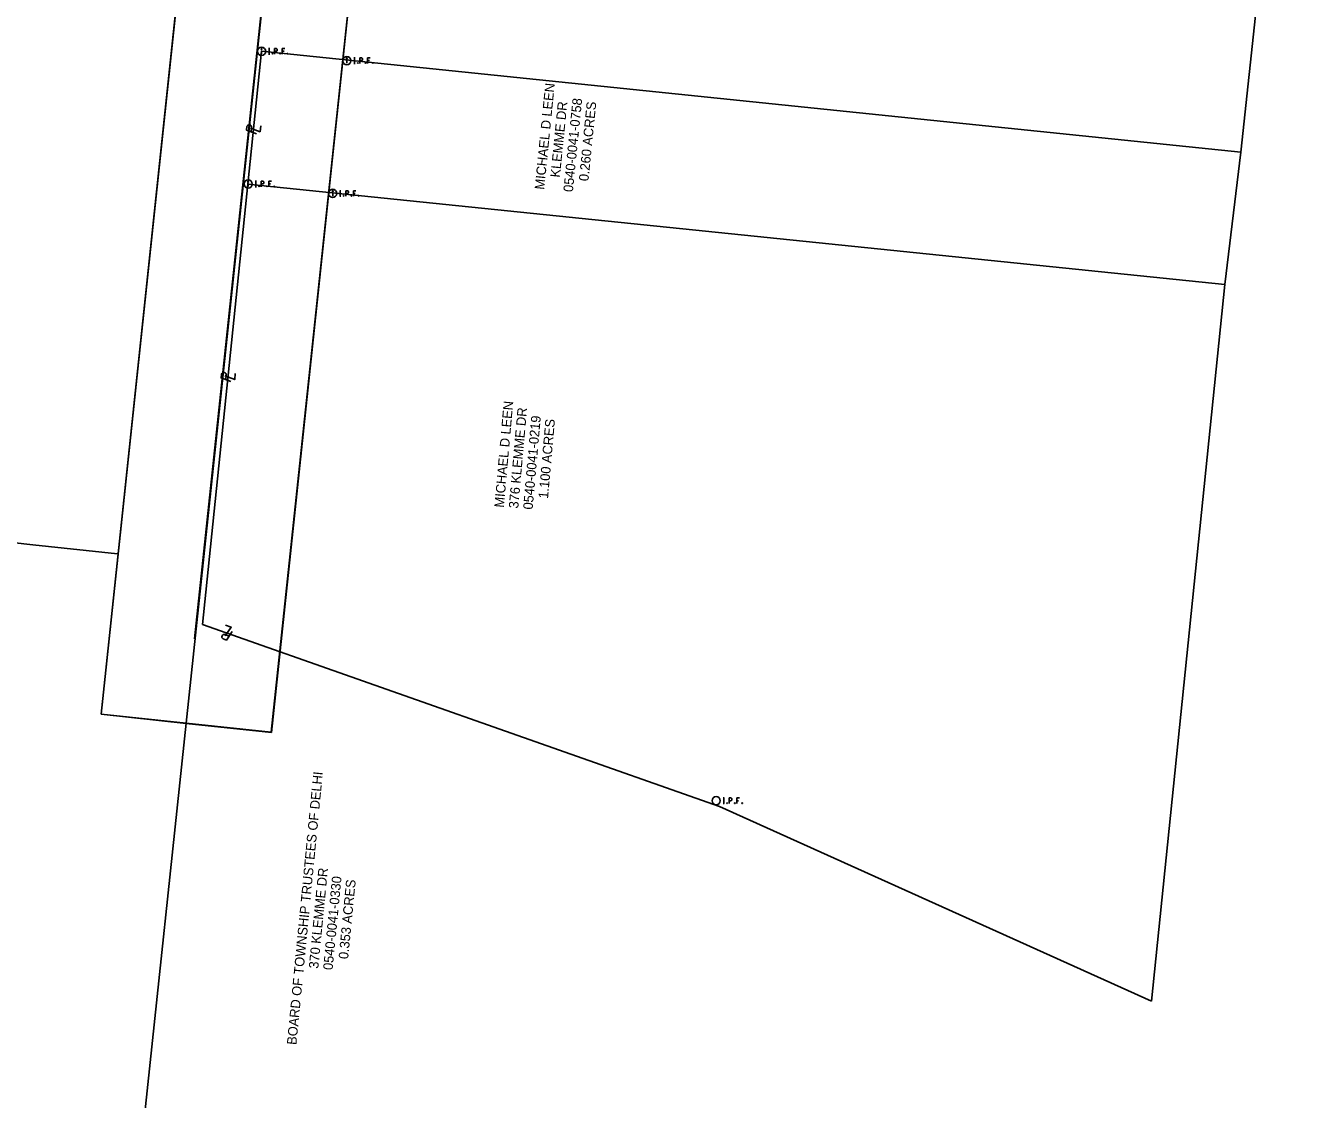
# Model space of a CAD drawing. Extents: x 1369159 to 1370720, y 404461 to 406422.
# Drawn here: x 1369919.6 to 1370296.1, y 405264.5 to 405577.8 of the extents above; entities that cross this region are included whole.
import ezdxf

# ---------------------------------------------------------------- set-up
doc = ezdxf.new("R2010")
doc.units = 0
for name, color, linetype in [('Default', 7, 'Continuous'), ('DR_P_Cells', 7, 'Continuous'), ('DR_P_Storm_Sewer', 7, 'Continuous'), ('GK_Drainage_Nodes', 7, 'Continuous'), ('PF_X_Ground_Line', 7, 'Continuous'), ('SC_Scratch1', 7, 'Continuous'), ('UT_X_Water', 7, 'Continuous'), ('XS_X_Pavt', 7, 'Continuous'), ('XS_X_Subgrade', 7, 'Continuous')]:
    doc.layers.add(name, color=color, linetype=linetype)

msp = doc.modelspace()

# ---------------------------------------------------------------- linework, layer by layer
at = {"layer": 'Default'}
for p, q in [((1369984.48, 405531.6), (1369988.46, 405570.34)), ((1369988.46, 405570.34), (1370274.45, 405540.93)), ((1370274.45, 405540.93), (1370269.79, 405502.27)), ((1369971.26, 405403.08), (1369984.48, 405531.6)), ((1370269.79, 405502.27), (1369984.48, 405531.61)), ((1370269.79, 405502.27), (1370248.29, 405293.15)), ((1370122.22, 405349.97), (1369971.26, 405403.08)), ((1369966.45, 405374.29), (1369897.64, 404726.71)), ((1370248.29, 405293.15), (1370122.22, 405349.97))]:
    msp.add_line(p, q, dxfattribs=at)
at = {"layer": 'DR_P_Cells'}
for p, q in [((1370077.92, 406421.94), (1369968.9, 405398.85)), ((1369966.45, 405374.29), (1369869.42, 404461.09))]:
    msp.add_line(p, q, dxfattribs=at)
at = {"layer": 'DR_P_Storm_Sewer'}
for p, q in [((1370274.45, 405540.93), (1370296.13, 405744.87)), ((1369985.42, 405546.84), (1369985.55, 405548.13)), ((1369986.12, 405547.58), (1369986.12, 405547.58)), ((1369977.98, 405474.54), (1369978.12, 405475.83)), ((1369978.68, 405475.27), (1369978.68, 405475.27)), ((1369978.99, 405399.7), (1369977.76, 405400.13)), ((1369978.44, 405400.55), (1369978.44, 405400.55))]:
    msp.add_line(p, q, dxfattribs=at)
for points in [[(1369986.96, 405546.26), (1369984.09, 405547.34), (1369984.2, 405548.37)], [(1369985.19, 405547.94), (1369988.05, 405546.85), (1369988.23, 405548.59)], [(1369979.52, 405473.96), (1369976.65, 405475.04), (1369976.76, 405476.06)], [(1369977.76, 405475.63), (1369980.62, 405474.54), (1369980.8, 405476.28)], [(1369977.87, 405399.74), (1369979.59, 405402.26), (1369977.95, 405402.84)], [(1369979.91, 405401.06), (1369978.19, 405398.52), (1369977.21, 405398.87)]]:
    msp.add_lwpolyline(points, dxfattribs=at)
for centre, start, end in [((1369984.87, 405548.2), 354.5992, 165.4563), ((1369977.43, 405475.89), 354.5992, 165.4563), ((1369977.54, 405399.48), 71.0908, 241.9479)]:
    msp.add_arc(centre, 0.69, start, end, dxfattribs=at)
at = {"layer": 'PF_X_Ground_Line'}
msp.add_lwpolyline([(1369946.39, 405423.64), (1369921.62, 405426.31), (1369638.99, 405458.25)], dxfattribs=at)
at = {"layer": 'SC_Scratch1'}
for p, q in [((1369988.46, 405570.46), (1369988.46, 405569.57)), ((1369990.49, 405571.14), (1369990.85, 405571.14)), ((1369990.49, 405569.54), (1369990.85, 405569.54)), ((1369990.67, 405569.54), (1369990.67, 405571.14)), ((1369991.56, 405569.68), (1369991.59, 405569.73)), ((1369991.56, 405569.61), (1369991.56, 405569.68)), ((1369991.59, 405569.56), (1369991.56, 405569.61)), ((1369991.59, 405569.73), (1369991.63, 405569.75)), ((1369991.63, 405569.54), (1369991.59, 405569.56)), ((1369991.63, 405569.75), (1369991.68, 405569.75)), ((1369991.68, 405569.54), (1369991.63, 405569.54)), ((1369991.68, 405569.75), (1369991.72, 405569.73)), ((1369991.72, 405569.56), (1369991.68, 405569.54)), ((1369991.72, 405569.73), (1369991.75, 405569.68)), ((1369991.75, 405569.61), (1369991.72, 405569.56)), ((1369991.75, 405569.68), (1369991.75, 405569.61)), ((1369992.23, 405569.54), (1369992.23, 405571.14)), ((1369992.23, 405571.14), (1369992.76, 405571.14)), ((1369992.76, 405570.36), (1369992.23, 405570.36)), ((1369992.76, 405571.14), (1369992.82, 405571.13)), ((1369992.85, 405570.37), (1369992.76, 405570.36)), ((1369992.82, 405571.13), (1369992.9, 405571.1)), ((1369992.91, 405570.4), (1369992.85, 405570.37)), ((1369992.9, 405571.1), (1369992.93, 405571.08)), ((1369992.94, 405570.42), (1369992.91, 405570.4)), ((1369992.93, 405571.08), (1369992.96, 405571.05)), ((1369992.98, 405570.46), (1369992.94, 405570.42)), ((1369992.96, 405571.05), (1369993.01, 405570.99)), ((1369993.03, 405570.55), (1369992.98, 405570.46)), ((1369993.01, 405570.99), (1369993.04, 405570.92)), ((1369993.05, 405570.62), (1369993.03, 405570.55)), ((1369993.04, 405570.92), (1369993.06, 405570.82)), ((1369993.06, 405570.67), (1369993.05, 405570.62)), ((1369993.06, 405570.82), (1369993.06, 405570.67)), ((1369993.81, 405569.68), (1369993.84, 405569.73)), ((1369993.81, 405569.61), (1369993.81, 405569.68)), ((1369993.84, 405569.56), (1369993.81, 405569.61)), ((1369993.84, 405569.73), (1369993.88, 405569.75)), ((1369993.88, 405569.54), (1369993.84, 405569.56)), ((1369993.88, 405569.75), (1369993.93, 405569.75)), ((1369993.93, 405569.54), (1369993.88, 405569.54)), ((1369993.93, 405569.75), (1369993.96, 405569.73)), ((1369993.96, 405569.56), (1369993.93, 405569.54)), ((1369993.96, 405569.73), (1369994, 405569.68)), ((1369994, 405569.61), (1369993.96, 405569.56)), ((1369994, 405569.68), (1369994, 405569.61)), ((1369995.24, 405571.14), (1369994.48, 405571.14)), ((1369994.48, 405571.14), (1369994.48, 405569.54)), ((1369994.48, 405570.36), (1369995.02, 405570.36)), ((1369995.96, 405569.68), (1369995.99, 405569.73)), ((1369995.96, 405569.61), (1369995.96, 405569.68)), ((1369995.99, 405569.56), (1369995.96, 405569.61)), ((1369995.99, 405569.73), (1369996.03, 405569.75)), ((1369996.03, 405569.54), (1369995.99, 405569.56)), ((1369996.03, 405569.75), (1369996.08, 405569.75)), ((1369996.08, 405569.54), (1369996.03, 405569.54)), ((1369996.08, 405569.75), (1369996.11, 405569.73)), ((1369996.11, 405569.56), (1369996.08, 405569.54)), ((1369996.11, 405569.73), (1369996.15, 405569.68)), ((1369996.15, 405569.61), (1369996.11, 405569.56)), ((1369996.15, 405569.68), (1369996.15, 405569.61)), ((1370015.4, 405568.41), (1370015.76, 405568.41)), ((1370015.58, 405566.81), (1370015.58, 405568.41)), ((1370017.14, 405566.81), (1370017.14, 405568.41)), ((1370017.14, 405568.41), (1370017.67, 405568.41)), ((1370017.67, 405568.41), (1370017.73, 405568.4)), ((1370017.73, 405568.4), (1370017.81, 405568.37)), ((1370017.81, 405568.37), (1370017.84, 405568.35)), ((1370017.84, 405568.35), (1370017.87, 405568.32)), ((1370017.87, 405568.32), (1370017.92, 405568.26)), ((1370017.92, 405568.26), (1370017.95, 405568.2)), ((1370017.95, 405568.2), (1370017.97, 405568.09)), ((1370017.97, 405567.94), (1370017.96, 405567.89)), ((1370017.97, 405568.09), (1370017.97, 405567.94)), ((1370020.15, 405568.41), (1370019.39, 405568.41)), ((1370019.39, 405568.41), (1370019.39, 405566.81)), ((1370013.37, 405567.73), (1370013.37, 405566.84)), ((1370015.4, 405566.81), (1370015.76, 405566.81)), ((1370016.47, 405566.95), (1370016.5, 405567)), ((1370016.47, 405566.89), (1370016.47, 405566.95)), ((1370016.5, 405566.84), (1370016.47, 405566.89)), ((1370016.5, 405567), (1370016.54, 405567.02)), ((1370016.54, 405566.81), (1370016.5, 405566.84)), ((1370016.54, 405567.02), (1370016.59, 405567.02)), ((1370016.59, 405566.81), (1370016.54, 405566.81)), ((1370016.59, 405567.02), (1370016.63, 405567)), ((1370016.63, 405566.84), (1370016.59, 405566.81)), ((1370016.63, 405567), (1370016.66, 405566.95)), ((1370016.66, 405566.89), (1370016.63, 405566.84)), ((1370016.66, 405566.95), (1370016.66, 405566.89)), ((1370017.67, 405567.63), (1370017.14, 405567.63)), ((1370017.76, 405567.64), (1370017.67, 405567.63)), ((1370017.82, 405567.67), (1370017.76, 405567.64)), ((1370017.85, 405567.69), (1370017.82, 405567.67)), ((1370017.89, 405567.73), (1370017.85, 405567.69)), ((1370017.94, 405567.82), (1370017.89, 405567.73)), ((1370017.96, 405567.89), (1370017.94, 405567.82)), ((1370018.72, 405566.95), (1370018.75, 405567)), ((1370018.72, 405566.89), (1370018.72, 405566.95)), ((1370018.75, 405566.84), (1370018.72, 405566.89)), ((1370018.75, 405567), (1370018.79, 405567.02)), ((1370018.79, 405566.81), (1370018.75, 405566.84)), ((1370018.79, 405567.02), (1370018.84, 405567.02)), ((1370018.84, 405566.81), (1370018.79, 405566.81)), ((1370018.84, 405567.02), (1370018.87, 405567)), ((1370018.87, 405566.84), (1370018.84, 405566.81)), ((1370018.87, 405567), (1370018.91, 405566.95)), ((1370018.91, 405566.89), (1370018.87, 405566.84)), ((1370018.91, 405566.95), (1370018.91, 405566.89)), ((1370019.39, 405567.63), (1370019.93, 405567.63)), ((1370020.87, 405566.95), (1370020.9, 405567)), ((1370020.87, 405566.89), (1370020.87, 405566.95)), ((1370020.9, 405566.84), (1370020.87, 405566.89)), ((1370020.9, 405567), (1370020.94, 405567.02)), ((1370020.94, 405566.81), (1370020.9, 405566.84)), ((1370020.94, 405567.02), (1370020.99, 405567.02)), ((1370020.99, 405566.81), (1370020.94, 405566.81)), ((1370020.99, 405567.02), (1370021.02, 405567)), ((1370021.02, 405566.84), (1370020.99, 405566.81)), ((1370021.02, 405567), (1370021.06, 405566.95)), ((1370021.06, 405566.89), (1370021.02, 405566.84)), ((1370021.06, 405566.95), (1370021.06, 405566.89)), ((1369984.55, 405531.73), (1369984.55, 405530.85)), ((1369986.58, 405532.42), (1369986.94, 405532.42)), ((1369986.58, 405530.82), (1369986.94, 405530.82)), ((1369986.76, 405530.82), (1369986.76, 405532.42)), ((1369987.65, 405530.95), (1369987.68, 405531.01)), ((1369987.65, 405530.89), (1369987.65, 405530.95)), ((1369987.68, 405530.84), (1369987.65, 405530.89)), ((1369987.68, 405531.01), (1369987.72, 405531.03)), ((1369987.72, 405530.82), (1369987.68, 405530.84)), ((1369987.72, 405531.03), (1369987.77, 405531.03)), ((1369987.77, 405530.82), (1369987.72, 405530.82)), ((1369987.77, 405531.03), (1369987.81, 405531.01)), ((1369987.81, 405530.84), (1369987.77, 405530.82)), ((1369987.81, 405531.01), (1369987.84, 405530.95)), ((1369987.84, 405530.89), (1369987.81, 405530.84)), ((1369987.84, 405530.95), (1369987.84, 405530.89)), ((1369988.32, 405530.82), (1369988.32, 405532.42)), ((1369988.32, 405532.42), (1369988.85, 405532.42)), ((1369988.85, 405531.63), (1369988.32, 405531.63)), ((1369988.85, 405532.42), (1369988.91, 405532.4)), ((1369988.94, 405531.65), (1369988.85, 405531.63)), ((1369988.91, 405532.4), (1369988.99, 405532.38)), ((1369989, 405531.67), (1369988.94, 405531.65)), ((1369988.99, 405532.38), (1369989.02, 405532.35)), ((1369989.03, 405531.7), (1369989, 405531.67)), ((1369989.02, 405532.35), (1369989.05, 405532.33)), ((1369989.07, 405531.74), (1369989.03, 405531.7)), ((1369989.05, 405532.33), (1369989.1, 405532.26)), ((1369989.12, 405531.82), (1369989.07, 405531.74)), ((1369989.1, 405532.26), (1369989.13, 405532.2)), ((1369989.14, 405531.9), (1369989.12, 405531.82)), ((1369989.13, 405532.2), (1369989.15, 405532.1)), ((1369989.15, 405531.95), (1369989.14, 405531.9)), ((1369989.15, 405532.1), (1369989.15, 405531.95)), ((1369989.9, 405530.95), (1369989.93, 405531.01)), ((1369989.9, 405530.89), (1369989.9, 405530.95)), ((1369989.93, 405530.84), (1369989.9, 405530.89)), ((1369989.93, 405531.01), (1369989.97, 405531.03)), ((1369989.97, 405530.82), (1369989.93, 405530.84)), ((1369989.97, 405531.03), (1369990.02, 405531.03)), ((1369990.02, 405530.82), (1369989.97, 405530.82)), ((1369990.02, 405531.03), (1369990.05, 405531.01)), ((1369990.05, 405530.84), (1369990.02, 405530.82)), ((1369990.05, 405531.01), (1369990.09, 405530.95)), ((1369990.09, 405530.89), (1369990.05, 405530.84)), ((1369990.09, 405530.95), (1369990.09, 405530.89)), ((1369991.33, 405532.42), (1369990.57, 405532.42)), ((1369990.57, 405532.42), (1369990.57, 405530.82)), ((1369990.57, 405531.63), (1369991.11, 405531.63)), ((1369992.05, 405530.95), (1369992.08, 405531.01)), ((1369992.05, 405530.89), (1369992.05, 405530.95)), ((1369992.08, 405530.84), (1369992.05, 405530.89)), ((1369992.08, 405531.01), (1369992.12, 405531.03)), ((1369992.12, 405530.82), (1369992.08, 405530.84)), ((1369992.12, 405531.03), (1369992.17, 405531.03)), ((1369992.17, 405530.82), (1369992.12, 405530.82)), ((1369992.17, 405531.03), (1369992.2, 405531.01)), ((1369992.2, 405530.84), (1369992.17, 405530.82)), ((1369992.2, 405531.01), (1369992.24, 405530.95)), ((1369992.24, 405530.89), (1369992.2, 405530.84)), ((1369992.24, 405530.95), (1369992.24, 405530.89)), ((1370009.24, 405528.98), (1370009.24, 405528.1)), ((1370011.27, 405529.67), (1370011.63, 405529.67)), ((1370011.27, 405528.07), (1370011.63, 405528.07)), ((1370011.45, 405528.07), (1370011.45, 405529.67)), ((1370012.34, 405528.21), (1370012.38, 405528.26)), ((1370012.34, 405528.14), (1370012.34, 405528.21)), ((1370012.38, 405528.09), (1370012.34, 405528.14)), ((1370012.38, 405528.26), (1370012.41, 405528.28)), ((1370012.41, 405528.07), (1370012.38, 405528.09)), ((1370012.41, 405528.28), (1370012.46, 405528.28)), ((1370012.46, 405528.07), (1370012.41, 405528.07)), ((1370012.46, 405528.28), (1370012.5, 405528.26)), ((1370012.5, 405528.09), (1370012.46, 405528.07)), ((1370012.5, 405528.26), (1370012.53, 405528.21)), ((1370012.53, 405528.14), (1370012.5, 405528.09)), ((1370012.53, 405528.21), (1370012.53, 405528.14)), ((1370013.02, 405528.07), (1370013.02, 405529.67)), ((1370013.02, 405529.67), (1370013.55, 405529.67)), ((1370013.55, 405528.89), (1370013.02, 405528.89)), ((1370013.55, 405529.67), (1370013.6, 405529.65)), ((1370013.63, 405528.9), (1370013.55, 405528.89)), ((1370013.6, 405529.65), (1370013.68, 405529.63)), ((1370013.69, 405528.92), (1370013.63, 405528.9)), ((1370013.68, 405529.63), (1370013.71, 405529.6)), ((1370013.72, 405528.95), (1370013.69, 405528.92)), ((1370013.71, 405529.6), (1370013.74, 405529.58)), ((1370013.77, 405528.99), (1370013.72, 405528.95)), ((1370013.74, 405529.58), (1370013.79, 405529.52)), ((1370013.81, 405529.07), (1370013.77, 405528.99)), ((1370013.79, 405529.52), (1370013.82, 405529.45)), ((1370013.83, 405529.15), (1370013.81, 405529.07)), ((1370013.82, 405529.45), (1370013.84, 405529.35)), ((1370013.84, 405529.2), (1370013.83, 405529.15)), ((1370013.84, 405529.35), (1370013.84, 405529.2)), ((1370014.59, 405528.21), (1370014.63, 405528.26)), ((1370014.59, 405528.14), (1370014.59, 405528.21)), ((1370014.63, 405528.09), (1370014.59, 405528.14)), ((1370014.63, 405528.26), (1370014.66, 405528.28)), ((1370014.66, 405528.07), (1370014.63, 405528.09)), ((1370014.66, 405528.28), (1370014.71, 405528.28)), ((1370014.71, 405528.07), (1370014.66, 405528.07)), ((1370014.71, 405528.28), (1370014.75, 405528.26)), ((1370014.75, 405528.09), (1370014.71, 405528.07)), ((1370014.75, 405528.26), (1370014.78, 405528.21)), ((1370014.78, 405528.14), (1370014.75, 405528.09)), ((1370014.78, 405528.21), (1370014.78, 405528.14)), ((1370016.03, 405529.67), (1370015.26, 405529.67)), ((1370015.26, 405529.67), (1370015.26, 405528.07)), ((1370015.26, 405528.89), (1370015.8, 405528.89)), ((1370016.74, 405528.21), (1370016.77, 405528.26)), ((1370016.74, 405528.14), (1370016.74, 405528.21)), ((1370016.77, 405528.09), (1370016.74, 405528.14)), ((1370016.77, 405528.26), (1370016.81, 405528.28)), ((1370016.81, 405528.07), (1370016.77, 405528.09)), ((1370016.81, 405528.28), (1370016.86, 405528.28)), ((1370016.86, 405528.07), (1370016.81, 405528.07)), ((1370016.86, 405528.28), (1370016.9, 405528.26)), ((1370016.9, 405528.09), (1370016.86, 405528.07)), ((1370016.9, 405528.26), (1370016.93, 405528.21)), ((1370016.93, 405528.14), (1370016.9, 405528.09)), ((1370016.93, 405528.21), (1370016.93, 405528.14)), ((1370123.23, 405352.43), (1370123.59, 405352.43)), ((1370123.23, 405350.83), (1370123.59, 405350.83)), ((1370123.41, 405350.83), (1370123.41, 405352.43)), ((1370124.3, 405350.96), (1370124.34, 405351.02)), ((1370124.3, 405350.9), (1370124.3, 405350.96)), ((1370124.34, 405350.85), (1370124.3, 405350.9)), ((1370124.34, 405351.02), (1370124.37, 405351.04)), ((1370124.37, 405350.83), (1370124.34, 405350.85)), ((1370124.37, 405351.04), (1370124.42, 405351.04)), ((1370124.42, 405350.83), (1370124.37, 405350.83)), ((1370124.42, 405351.04), (1370124.46, 405351.02)), ((1370124.46, 405350.85), (1370124.42, 405350.83)), ((1370124.46, 405351.02), (1370124.49, 405350.96)), ((1370124.49, 405350.9), (1370124.46, 405350.85)), ((1370124.49, 405350.96), (1370124.49, 405350.9)), ((1370124.98, 405350.83), (1370124.98, 405352.43)), ((1370124.98, 405352.43), (1370125.51, 405352.43)), ((1370125.51, 405351.64), (1370124.98, 405351.64)), ((1370125.51, 405352.43), (1370125.56, 405352.41)), ((1370125.59, 405351.66), (1370125.51, 405351.64)), ((1370125.56, 405352.41), (1370125.64, 405352.39)), ((1370125.65, 405351.68), (1370125.59, 405351.66)), ((1370125.64, 405352.39), (1370125.67, 405352.36)), ((1370125.68, 405351.71), (1370125.65, 405351.68)), ((1370125.67, 405352.36), (1370125.7, 405352.34)), ((1370125.73, 405351.75), (1370125.68, 405351.71)), ((1370125.7, 405352.34), (1370125.75, 405352.27)), ((1370125.77, 405351.83), (1370125.73, 405351.75)), ((1370125.75, 405352.27), (1370125.78, 405352.21)), ((1370125.79, 405351.91), (1370125.77, 405351.83)), ((1370125.78, 405352.21), (1370125.8, 405352.11)), ((1370125.8, 405351.96), (1370125.79, 405351.91)), ((1370125.8, 405352.11), (1370125.8, 405351.96)), ((1370126.55, 405350.96), (1370126.59, 405351.02)), ((1370126.55, 405350.9), (1370126.55, 405350.96)), ((1370126.59, 405350.85), (1370126.55, 405350.9)), ((1370126.59, 405351.02), (1370126.62, 405351.04)), ((1370126.62, 405350.83), (1370126.59, 405350.85)), ((1370126.62, 405351.04), (1370126.67, 405351.04)), ((1370126.67, 405350.83), (1370126.62, 405350.83)), ((1370126.67, 405351.04), (1370126.71, 405351.02)), ((1370126.71, 405350.85), (1370126.67, 405350.83)), ((1370126.71, 405351.02), (1370126.74, 405350.96)), ((1370126.74, 405350.9), (1370126.71, 405350.85)), ((1370126.74, 405350.96), (1370126.74, 405350.9)), ((1370127.99, 405352.43), (1370127.22, 405352.43)), ((1370127.22, 405352.43), (1370127.22, 405350.83)), ((1370127.22, 405351.64), (1370127.76, 405351.64)), ((1370128.7, 405350.96), (1370128.73, 405351.02)), ((1370128.7, 405350.9), (1370128.7, 405350.96)), ((1370128.73, 405350.85), (1370128.7, 405350.9)), ((1370128.73, 405351.02), (1370128.77, 405351.04)), ((1370128.77, 405350.83), (1370128.73, 405350.85)), ((1370128.77, 405351.04), (1370128.82, 405351.04)), ((1370128.82, 405350.83), (1370128.77, 405350.83)), ((1370128.82, 405351.04), (1370128.86, 405351.02)), ((1370128.86, 405350.85), (1370128.82, 405350.83)), ((1370128.86, 405351.02), (1370128.89, 405350.96)), ((1370128.89, 405350.9), (1370128.86, 405350.85)), ((1370128.89, 405350.96), (1370128.89, 405350.9))]:
    msp.add_line(p, q, dxfattribs=at)
for centre, radius in [((1369988.46, 405570.34), 1.2), ((1369988.46, 405570.99), 0.16), ((1370013.37, 405567.61), 1.2), ((1370013.37, 405568.26), 0.16), ((1369984.55, 405531.62), 1.2), ((1369984.55, 405532.27), 0.16), ((1370009.24, 405528.87), 1.2), ((1370009.24, 405529.52), 0.16), ((1370121.22, 405351.63), 1.2)]:
    msp.add_circle(centre, radius, dxfattribs=at)
at = {"layer": 'UT_X_Water'}
msp.add_line((1369966.46, 405374.2), (1369941.6, 405376.85), dxfattribs=at)
msp.add_lwpolyline([(1369941.6, 405376.85), (1369965.4, 405600.58), (1370015.12, 405595.3), (1369991.32, 405371.56), (1369966.44, 405374.21)], dxfattribs=at)
at = {"layer": 'XS_X_Pavt'}
msp.add_line((1370023.41, 405910.39), (1369966.45, 405374.29), dxfattribs=at)
at = {"layer": 'XS_X_Subgrade'}
for p, q in [((1370043.12, 405859.34), (1369991.31, 405371.65)), ((1369992.21, 405853.35), (1369941.59, 405376.93)), ((1369941.59, 405376.93), (1369966.45, 405374.29)), ((1369966.45, 405374.29), (1369991.31, 405371.65))]:
    msp.add_line(p, q, dxfattribs=at)

# ---------------------------------------------------------------- texts
at = {"layer": 'GK_Drainage_Nodes'}
for s, rotation, p in [('MICHAEL D LEEN', 84.2529, (1370070.98, 405529.87)), ('KLEMME DR', 84.2529, (1370075.56, 405533.41)), ('0540-0041-0758', 84.2529, (1370079.35, 405529.18)), ('0.260 ACRES', 84.2529, (1370083.89, 405532.34)), ('MICHAEL D LEEN', 84.9191, (1370059.21, 405437.08)), ('376 KLEMME DR', 84.9191, (1370063.41, 405436.84)), ('0540-0041-0219', 84.9191, (1370067.6, 405436.52)), ('1.100 ACRES', 84.9191, (1370072.1, 405439.7)), ('BOARD OF TOWNSHIP TRUSTEES OF DELHI', 84.4305, (1369998.62, 405280.28)), ('370 KLEMME DR', 84.4305, (1370005.01, 405302.52)), ('0540-0041-0330', 84.4305, (1370009.19, 405302.12)), ('0.353 ACRES', 84.4305, (1370013.72, 405305.31))]:
    msp.add_text(s, height=2.8, rotation=rotation, dxfattribs=at).set_placement(p)

doc.saveas('drawing.dxf')
